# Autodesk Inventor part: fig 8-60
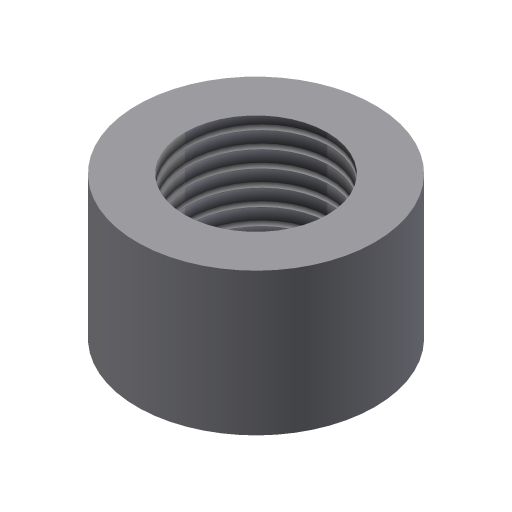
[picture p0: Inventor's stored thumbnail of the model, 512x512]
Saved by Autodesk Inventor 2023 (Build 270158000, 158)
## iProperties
Created: 2002-01
Part Number: fig 8-60
Document SubType Name: Modeling
Designer: ***
Density: 1 g/cm^3
Material: Generic
Appearance: Default
Control State: 0
Master: False
Checked Out: False
Shininess: 77.0
Length Units: 11269
Angle Units: 11279
Time Units: 11290
Mass Units: 11283
Length Display Precision: 3
Angle Display Precision: 2
Compacted: True
Density: 0.0
Volumn: 0.0
Area: 0.0
PropertySet Name: Model Information
Author: ***
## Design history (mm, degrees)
sketch "Sketch1"
  geometry: C1 r 25 at (0, 0); C2 r 15 at (0, 0)
  constraints: 2 centre point, 1 coincident
  dimensions: "d0" = 50 diameter of C1; "d1" = 30 diameter of C2
extrude "Extrusion1" new body sketch "Sketch1" distance "d2" = 30; taper "d3" = 0 deg
thread "Thread5" dims "d12" = 10, "d13" = 0
body "Solid1"
